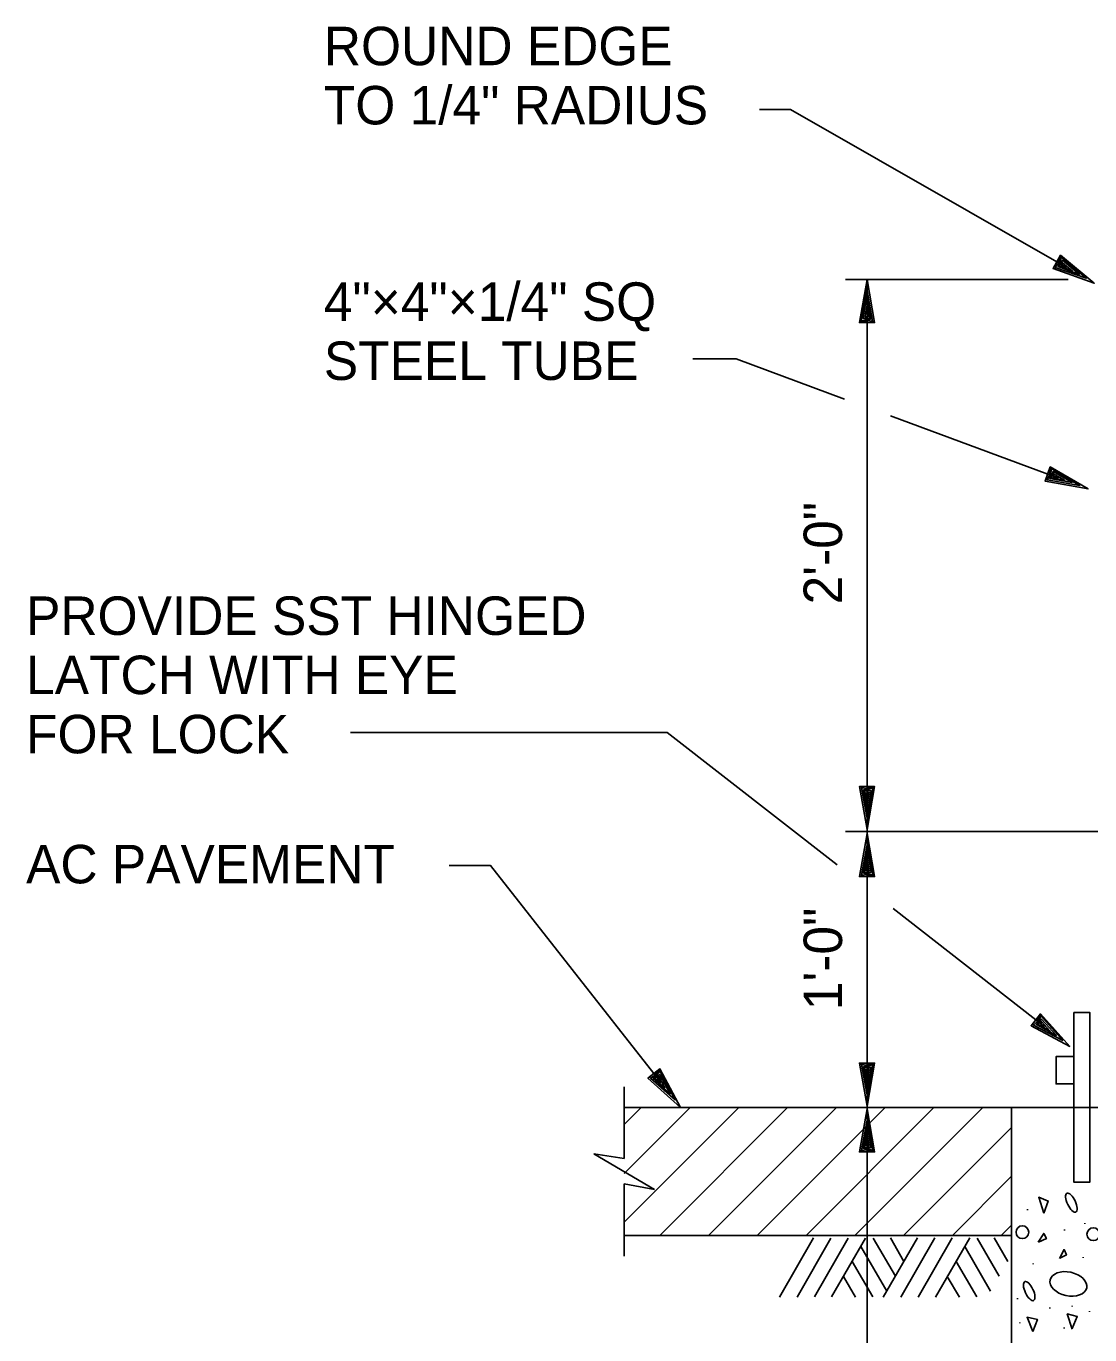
# Model space of a CAD drawing. Extents: x -119017 to -116080, y -104449 to -102845.
# Drawn here: x -117921.3 to -117755.4, y -103410.1 to -103206 of the extents above; entities that cross this region are included whole.
import ezdxf

# ---------------------------------------------------------------- set-up
doc = ezdxf.new("R2010")
doc.units = 0
for name, color, linetype in [('C-DETL-MEDM', 7, 'Continuous'), ('C-DIMS', 7, 'Continuous'), ('C-MARK', 7, 'Continuous'), ('C-PATT', 7, 'Continuous'), ('C-TEXT', 7, 'Continuous'), ('Misc CnstDet(22)', 7, 'Continuous')]:
    doc.layers.add(name, color=color, linetype=linetype)

msp = doc.modelspace()

# ---------------------------------------------------------------- linework, layer by layer
at = {"layer": 'C-DETL-MEDM'}
for p, q in [((-117828.02, -103374.64), (-117753.26, -103374.64)), ((-117767.61, -103503.76), (-117767.61, -103374.64)), ((-117828.02, -103394.59), (-117767.57, -103394.59))]:
    msp.add_line(p, q, dxfattribs=at)
msp.add_lwpolyline([(-117757.91, -103359.8), (-117755.42, -103359.8), (-117755.42, -103386.29), (-117757.91, -103386.29)], close=True, dxfattribs=at)
msp.add_lwpolyline([(-117757.91, -103366.7), (-117760.67, -103366.7), (-117760.67, -103370.96), (-117757.91, -103370.96)], dxfattribs=at)
at = {"layer": 'C-DIMS'}
for p, q in [((-117758.78, -103245.52), (-117793.52, -103245.52)), ((-117790.16, -103245.52), (-117790.16, -103503.76)), ((-117749.45, -103331.6), (-117793.52, -103331.6))]:
    msp.add_line(p, q, dxfattribs=at)
for points in [[(-117791.34, -103252.24), (-117788.97, -103252.24), (-117790.16, -103245.52), (-117791.34, -103252.24), (-117790.16, -103251.92), (-117789.3, -103252.03), (-117790.21, -103246.97), (-117791.13, -103252.03), (-117790.16, -103251.71), (-117789.62, -103251.71), (-117790.21, -103248.21), (-117790.8, -103251.6), (-117789.78, -103251.55), (-117790.16, -103249.45), (-117790.48, -103251.38), (-117790, -103251.22), (-117790.16, -103250.52), (-117790.16, -103252.24)], [(-117788.97, -103324.58), (-117791.34, -103324.58), (-117790.16, -103331.3), (-117788.97, -103324.58), (-117790.16, -103324.9), (-117791.02, -103324.79), (-117790.1, -103329.85), (-117789.19, -103324.79), (-117790.16, -103325.11), (-117790.7, -103325.11), (-117790.1, -103328.61), (-117789.51, -103325.22), (-117790.53, -103325.28), (-117790.16, -103327.37), (-117789.83, -103325.44), (-117790.32, -103325.6), (-117790.16, -103326.3), (-117790.16, -103324.58)], [(-117788.97, -103338.62), (-117791.34, -103338.62), (-117790.16, -103331.89), (-117788.97, -103338.62), (-117790.16, -103338.3), (-117791.02, -103338.4), (-117790.1, -103333.35), (-117789.19, -103338.4), (-117790.16, -103338.08), (-117790.7, -103338.08), (-117790.1, -103334.58), (-117789.51, -103337.97), (-117790.53, -103337.92), (-117790.16, -103335.82), (-117789.83, -103337.76), (-117790.32, -103337.6), (-117790.16, -103336.9), (-117790.16, -103338.62)], [(-117788.97, -103367.7), (-117791.34, -103367.7), (-117790.16, -103374.42), (-117788.97, -103367.7), (-117790.16, -103368.02), (-117791.02, -103367.91), (-117790.1, -103372.97), (-117789.19, -103367.91), (-117790.16, -103368.24), (-117790.7, -103368.24), (-117790.1, -103371.73), (-117789.51, -103368.34), (-117790.53, -103368.4), (-117790.16, -103370.5), (-117789.83, -103368.56), (-117790.32, -103368.72), (-117790.16, -103369.42), (-117790.16, -103367.7)], [(-117788.97, -103381.57), (-117791.34, -103381.57), (-117790.16, -103374.85), (-117788.97, -103381.57), (-117790.16, -103381.25), (-117791.02, -103381.36), (-117790.1, -103376.3), (-117789.19, -103381.36), (-117790.16, -103381.04), (-117790.7, -103381.04), (-117790.1, -103377.54), (-117789.51, -103380.93), (-117790.53, -103380.87), (-117790.16, -103378.78), (-117789.83, -103380.71), (-117790.32, -103380.55), (-117790.16, -103379.85), (-117790.16, -103381.57)]]:
    msp.add_lwpolyline(points, dxfattribs=at)
at = {"layer": 'C-MARK'}
for p, q in [((-117828.02, -103371.41), (-117828.02, -103382.57)), ((-117828.02, -103382.57), (-117832.75, -103381.87)), ((-117823.28, -103387.41), (-117832.75, -103381.87)), ((-117828.02, -103382.57), (-117828.02, -103382.57)), ((-117828.02, -103386.55), (-117828.02, -103397.82)), ((-117823.28, -103387.41), (-117828.02, -103386.55)), ((-117828.02, -103386.55), (-117828.02, -103386.55))]:
    msp.add_line(p, q, dxfattribs=at)
for points in [[(-117806.95, -103219.01), (-117802.11, -103219.01), (-117760.57, -103242.76)], [(-117817.3, -103257.9), (-117810.58, -103257.9), (-117793.66, -103264.15)], [(-117786.52, -103266.79), (-117761.99, -103275.85)], [(-117870.71, -103316.15), (-117821.3, -103316.15), (-117794.81, -103336.81)], [(-117855.32, -103336.91), (-117848.86, -103336.91), (-117823.39, -103369.35)], [(-117786.09, -103343.61), (-117763.84, -103360.96)]]:
    msp.add_lwpolyline(points, dxfattribs=at)
at = {"layer": 'C-PATT'}
for p, q in [((-117828.02, -103374.68), (-117827.97, -103374.64)), ((-117828.01, -103377.29), (-117825.37, -103374.64)), ((-117828.01, -103384.9), (-117817.76, -103374.64)), ((-117828.01, -103392.5), (-117810.15, -103374.64)), ((-117822.49, -103394.59), (-117802.54, -103374.64)), ((-117814.88, -103394.59), (-117794.93, -103374.64)), ((-117807.27, -103394.59), (-117787.32, -103374.64)), ((-117799.67, -103394.59), (-117779.72, -103374.64)), ((-117792.06, -103394.59), (-117772.11, -103374.64)), ((-117784.45, -103394.59), (-117767.61, -103377.75)), ((-117776.84, -103394.59), (-117767.61, -103385.36)), ((-117765.14, -103390.62), (-117765.14, -103390.51)), ((-117769.23, -103394.59), (-117767.61, -103392.97)), ((-117759.38, -103393.79), (-117759.38, -103393.68)), ((-117756.21, -103392.77), (-117756.21, -103392.66)), ((-117803.79, -103404.2), (-117798.48, -103394.98)), ((-117801.07, -103404.2), (-117795.79, -103395)), ((-117798.37, -103404.16), (-117793.12, -103395.03)), ((-117795.7, -103404.16), (-117790.4, -103395.03)), ((-117787.09, -103403.27), (-117791.13, -103396.3)), ((-117785.74, -103400.94), (-117789.21, -103395)), ((-117787.62, -103404.2), (-117782.28, -103394.98)), ((-117784.4, -103398.63), (-117786.52, -103394.98)), ((-117784.88, -103404.2), (-117779.56, -103394.98)), ((-117782.16, -103404.2), (-117776.86, -103394.98)), ((-117779.46, -103404.2), (-117774.14, -103394.98)), ((-117770.92, -103403.27), (-117774.92, -103396.3)), ((-117769.55, -103400.94), (-117772.98, -103395)), ((-117768.21, -103398.63), (-117770.31, -103394.98)), ((-117756.48, -103398.09), (-117756.48, -103397.98)), ((-117789.26, -103404.16), (-117792.48, -103398.63)), ((-117773.05, -103404.16), (-117776.27, -103398.63)), ((-117764.23, -103399.06), (-117764.23, -103398.95)), ((-117791.96, -103404.2), (-117793.85, -103400.98)), ((-117775.76, -103404.2), (-117777.64, -103400.98)), ((-117766.7, -103404.5), (-117766.7, -103404.39)), ((-117761.64, -103405.95), (-117761.64, -103405.84)), ((-117758.15, -103405.68), (-117758.15, -103405.57)), ((-117755.46, -103406.49), (-117755.46, -103406.38)), ((-117766.32, -103408.26), (-117766.32, -103408.15)), ((-117759.44, -103409.07), (-117759.44, -103408.96))]:
    msp.add_line(p, q, dxfattribs=at)
for points in [[(-117762.61, -103391.1), (-117763.37, -103388.62), (-117761.91, -103389.22), (-117762.61, -103391.1)], [(-117763.42, -103395.62), (-117762.18, -103395.08), (-117762.61, -103394.27), (-117763.47, -103395.62)], [(-117760.08, -103398.15), (-117759.06, -103397.61), (-117759.44, -103396.8), (-117760.14, -103398.2)], [(-117764.33, -103409.55), (-117765.2, -103407.35), (-117763.58, -103407.67), (-117764.33, -103409.55)], [(-117758.15, -103409.18), (-117758.95, -103406.81), (-117757.39, -103407.24), (-117758.15, -103409.12)]]:
    msp.add_lwpolyline(points, dxfattribs=at)
for centre in [(-117765.93, -103394.08), (-117754.87, -103394.39)]:
    msp.add_circle(centre, 0.997, dxfattribs=at)
for centre, major_axis, ratio in [((-117758.29, -103389.48), (0.69, -1.47), 0.393469), ((-117758.76, -103402.14), (-2.85, 0.63), 0.634119), ((-117764.87, -103403.26), (0.69, -1.47), 0.393469)]:
    msp.add_ellipse(centre, major_axis=major_axis, ratio=ratio, dxfattribs=at)
at = {"layer": 'C-TEXT'}
for points in [[(-117759.99, -103241.74), (-117761.16, -103243.79), (-117754.74, -103246.1), (-117759.99, -103241.74), (-117760.29, -103242.92), (-117760.82, -103243.62), (-117755.97, -103245.33), (-117759.91, -103242.03), (-117760.11, -103243.03), (-117760.37, -103243.5), (-117757.05, -103244.72), (-117759.69, -103242.52), (-117760.15, -103243.44), (-117758.15, -103244.15), (-117759.67, -103242.91), (-117759.77, -103243.41), (-117759.08, -103243.62), (-117760.57, -103242.76)], [(-117761.58, -103274.74), (-117762.4, -103276.96), (-117755.68, -103278.18), (-117761.58, -103274.74), (-117761.68, -103275.96), (-117762.08, -103276.73), (-117757.02, -103277.62), (-117761.45, -103275.01), (-117761.48, -103276.03), (-117761.67, -103276.54), (-117758.18, -103277.19), (-117761.16, -103275.46), (-117761.46, -103276.44), (-117759.36, -103276.82), (-117761.07, -103275.84), (-117761.08, -103276.35), (-117760.37, -103276.44), (-117761.99, -103275.85)], [(-117763.11, -103360.03), (-117764.57, -103361.89), (-117758.54, -103365.1), (-117763.11, -103360.03), (-117763.59, -103361.16), (-117764.2, -103361.77), (-117759.65, -103364.16), (-117763.08, -103360.33), (-117763.42, -103361.29), (-117763.75, -103361.71), (-117760.62, -103363.4), (-117762.93, -103360.85), (-117763.52, -103361.69), (-117761.63, -103362.68), (-117762.96, -103361.23), (-117763.13, -103361.71), (-117762.48, -103362.02), (-117763.84, -103360.96)], [(-117822.46, -103368.62), (-117824.32, -103370.08), (-117819.23, -103374.64), (-117822.46, -103368.62), (-117823.19, -103369.6), (-117823.93, -103370.05), (-117820.09, -103373.46), (-117822.49, -103368.92), (-117823.06, -103369.77), (-117823.48, -103370.1), (-117820.85, -103372.49), (-117822.48, -103369.46), (-117823.25, -103370.13), (-117821.66, -103371.55), (-117822.6, -103369.82), (-117822.88, -103370.25), (-117822.32, -103370.7), (-117823.39, -103369.35)]]:
    msp.add_lwpolyline(points, dxfattribs=at)

# ---------------------------------------------------------------- texts
at = {"layer": 'Misc CnstDet(22)'}
for s, p in [('ROUND EDGE ', (-117874.85, -103212.1)), ('TO 1/4" RADIUS', (-117874.85, -103221.33)), ('4"×4"×1/4" SQ', (-117874.85, -103251.96)), ('STEEL TUBE', (-117874.85, -103261.18)), ('PROVIDE SST HINGED', (-117921.28, -103300.94)), ('LATCH WITH EYE', (-117921.28, -103310.17)), ('FOR LOCK', (-117921.28, -103319.4)), ('AC PAVEMENT', (-117921.28, -103339.68))]:
    msp.add_text(s, height=6, dxfattribs=at).set_placement(p)
for s, p in [('2\'-0"', (-117794.05, -103296.18)), ('1\'-0"', (-117794.05, -103359.45))]:
    msp.add_text(s, height=6, rotation=90, dxfattribs=at).set_placement(p)

doc.saveas('drawing.dxf')
